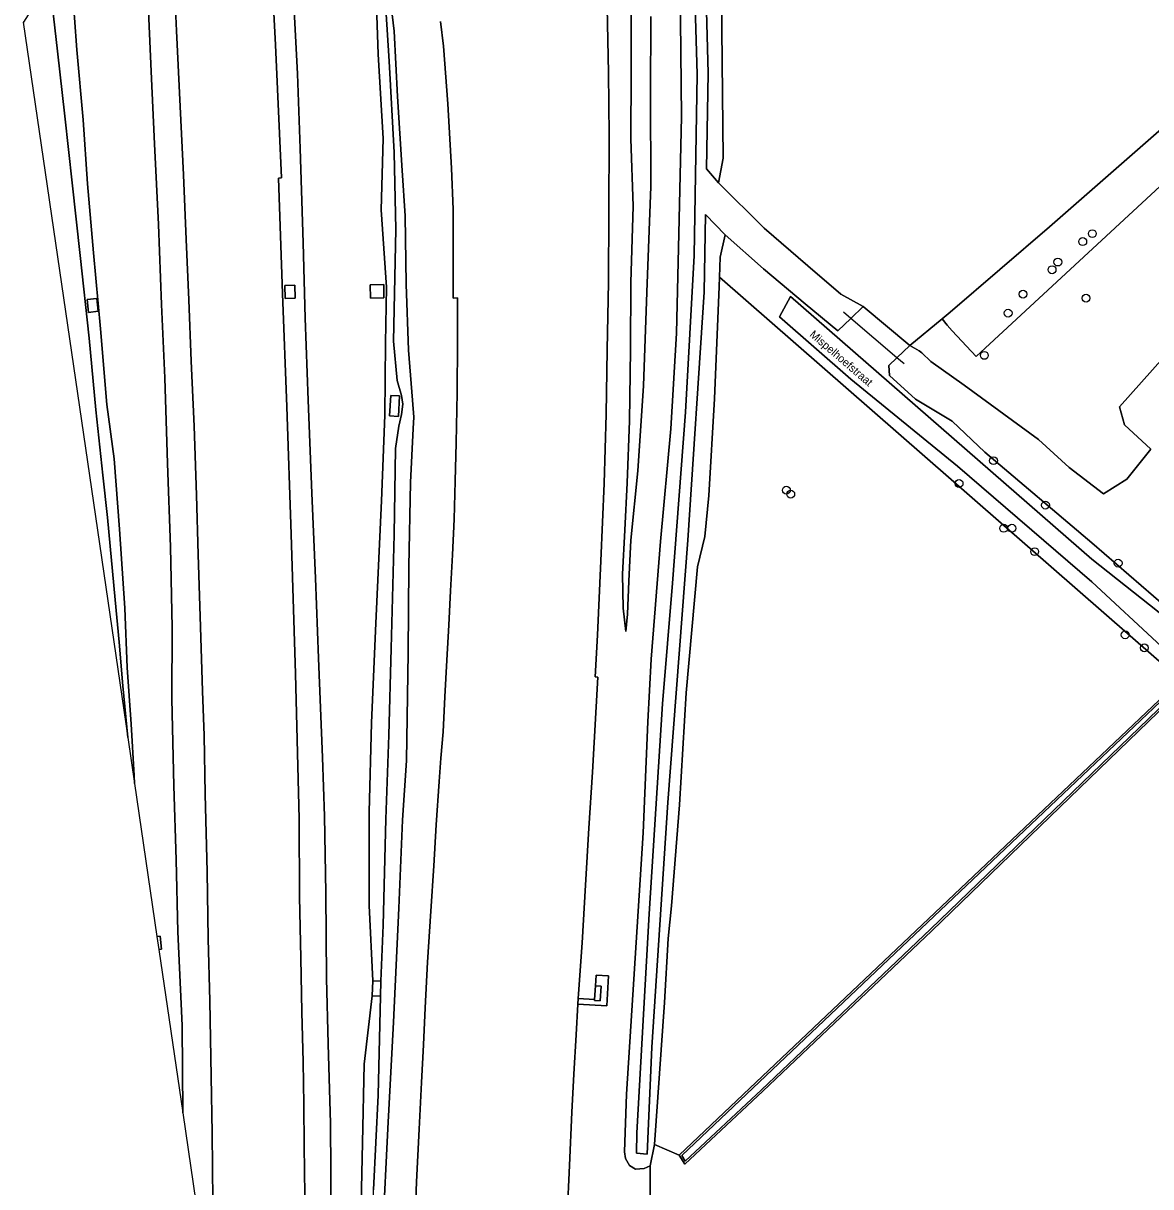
# Model space of a CAD drawing. Extents: x 156141 to 158132, y 385651 to 388333.
# Drawn here: x 156199.9 to 156340.7, y 386932.5 to 387077.9 of the extents above; entities that cross this region are included whole.
import ezdxf

# ---------------------------------------------------------------- set-up
doc = ezdxf.new("R2010")
doc.units = 0
for name, color, linetype in [('IMGEO_Berm_groen', 7, 'Continuous'), ('IMGEO_Boom', 7, 'Continuous'), ('IMGEO_Bouwland', 7, 'Continuous'), ('IMGEO_Duiker', 7, 'Continuous'), ('IMGEO_Grasland_overig', 7, 'Continuous'), ('IMGEO_Groenvoorziening', 7, 'Continuous'), ('IMGEO_Houtwal', 7, 'Continuous'), ('IMGEO_Loofbos', 7, 'Continuous'), ('IMGEO_Oever', 7, 'Continuous'), ('IMGEO_Openbare_ruimte_label', 7, 'Continuous'), ('IMGEO_Rijbaan_autosnelweg', 7, 'Continuous'), ('IMGEO_Rijbaan_lokaal_open', 7, 'Continuous'), ('IMGEO_Terreindeel_gesloten', 7, 'Continuous'), ('IMGEO_Terreindeel_open', 7, 'Continuous'), ('IMGEO_Waterloop', 7, 'Continuous')]:
    doc.layers.add(name, color=color, linetype=linetype)

msp = doc.modelspace()

# ---------------------------------------------------------------- linework, layer by layer
at = {"layer": 'IMGEO_Berm_groen'}
for points in [[(156230.11, 387099.04), (156231.36, 387075.16), (156232.14, 387058.58), (156231.74, 387058.51), (156232.25, 387044.13), (156232.79, 387029.97), (156233.33, 387014.06), (156233.86, 386996.59), (156234.31, 386978.5), (156234.39, 386968.76), (156234.53, 386961.13), (156234.68, 386954.33), (156234.83, 386948.15), (156234.92, 386942.8), (156234.97, 386937.65), (156235.04, 386931.47)], [(156223.54, 386930.73), (156223.44, 386939.22), (156223.32, 386946.32), (156223.18, 386955.74), (156222.96, 386963.51), (156222.84, 386971.85), (156222.6, 386981.59), (156222.44, 386988.92), (156222.25, 386994.44), (156222.02, 387002.46), (156221.73, 387011.49), (156221.49, 387018.92), (156221.19, 387027.55), (156220.83, 387035.68), (156220.53, 387043.33), (156220.22, 387050.85), (156219.87, 387058.94), (156219.48, 387067.48), (156219.02, 387076.94), (156218.55, 387087.03)], [(156241.87, 386920.87), (156242.26, 386938), (156242.44, 386947.86), (156243.46, 386956.36), (156243.54, 386958.27), (156243.07, 386967.68), (156243.07, 386979.31), (156243.38, 386990.48), (156243.89, 387002.95), (156244.63, 387018.21), (156245.04, 387028.93), (156245.11, 387037.93), (156245.22, 387044.91), (156244.56, 387054.56), (156244.81, 387063.48), (156244.21, 387074.03), (156243.84, 387084.86)], [(156243.84, 387084.86), (156244.21, 387074.03), (156244.81, 387063.48), (156244.56, 387054.56), (156245.22, 387044.91), (156245.11, 387037.93), (156245.04, 387028.93), (156244.63, 387018.21), (156243.89, 387002.95), (156243.38, 386990.48), (156243.07, 386979.31), (156243.07, 386967.68), (156243.54, 386958.27), (156244.55, 386958.23), (156244.82, 386965.2), (156245.14, 386978.43), (156245.51, 386988.93), (156245.81, 386999.78), (156246.19, 387014.02), (156246.37, 387024.74), (156246.8, 387027.55), (156247.13, 387029), (156247.27, 387030.28), (156247.12, 387031.38), (156246.57, 387033.25), (156246.13, 387038.15), (156246.39, 387052.12), (156246.2, 387061.74), (156245.58, 387073.13), (156244.88, 387084.28)], [(156244.88, 387084.28), (156245.58, 387073.13), (156246.2, 387061.74), (156246.39, 387052.12), (156246.13, 387038.15), (156246.57, 387033.25), (156247.12, 387031.38), (156247.27, 387030.28), (156247.13, 387029), (156246.8, 387027.55), (156246.37, 387024.74), (156246.19, 387014.02), (156245.81, 386999.78), (156245.51, 386988.93), (156245.14, 386978.43), (156244.82, 386965.2), (156244.55, 386958.23), (156244.48, 386956.32), (156244.2, 386943.98), (156243.61, 386932.16)], [(156245.34, 387084.2), (156246.21, 387076.87), (156246.63, 387068.74), (156247.18, 387059.46), (156247.56, 387053.83), (156247.69, 387045.26), (156247.98, 387037.03), (156248.48, 387030.8), (156248.66, 387028.65), (156248.58, 387027.23), (156248.22, 387020.49), (156248.04, 387010.02), (156247.94, 386999.21), (156247.74, 386985.78), (156247.23, 386978.34), (156246.79, 386967.32), (156246.13, 386953.1), (156245.41, 386939.82), (156244.78, 386927.16)], [(156244.78, 386927.16), (156245.41, 386939.82), (156246.13, 386953.1), (156246.79, 386967.32), (156247.23, 386978.34), (156247.74, 386985.78), (156247.94, 386999.21), (156248.04, 387010.02), (156248.22, 387020.49), (156248.58, 387027.23), (156248.66, 387028.65), (156248.48, 387030.8), (156247.98, 387037.03), (156247.69, 387045.26), (156247.56, 387053.83), (156247.18, 387059.46), (156246.63, 387068.74), (156246.21, 387076.87), (156245.34, 387084.2)], [(156203.13, 387083.18), (156204.13, 387074.37), (156205.05, 387066.27), (156205.96, 387057.93), (156206.98, 387048.86), (156208.1, 387038.55), (156208.94, 387029.58), (156209.8, 387021.43), (156210.39, 387016.14), (156211.32, 387005.84), (156211.83, 387000.55), (156212.31, 386995.1), (156212.93, 386988.66), (156213.77, 386982.89), (156213.7, 386983.92), (156213.33, 386990.31), (156212.83, 386997.39), (156212.55, 387004.81), (156211.9, 387014.67), (156211.22, 387023.44), (156210.3, 387030.23), (156209.51, 387039.71), (156208.64, 387049.21), (156207.9, 387057.8), (156207.35, 387065.8), (156206.54, 387074.54), (156205.96, 387082.59)], [(156205.96, 387082.59), (156206.54, 387074.54), (156207.35, 387065.8), (156207.9, 387057.8), (156208.64, 387049.21), (156209.51, 387039.71), (156210.3, 387030.23), (156211.22, 387023.44), (156211.9, 387014.67), (156212.55, 387004.81), (156212.83, 386997.39), (156213.33, 386990.31), (156213.7, 386983.92), (156213.77, 386982.89), (156216.56, 386963.8), (156216.96, 386963.84), (156217.13, 386962.19), (156216.8, 386962.16), (156219.79, 386941.75), (156219.73, 386952.67), (156219.17, 386964.39), (156218.98, 386973.36), (156218.66, 386982.61), (156218.42, 386993.46), (156218.47, 387002.34), (156218.24, 387012.48), (156217.88, 387022.86), (156217.54, 387033.57), (156217.13, 387042.74), (156216.75, 387052.73), (156216.25, 387062.81), (156215.82, 387071.83), (156215.43, 387081.34)], [(156278.19, 386927.66), (156278.18, 386935.13), (156277.42, 386934.81), (156276.36, 386934.73), (156275.59, 386935.17), (156275.11, 386936.04), (156274.96, 386936.9), (156275.23, 386944.09), (156276.56, 386965), (156277.31, 386976.73), (156277.9, 386990.61), (156278.32, 386998.43), (156279.46, 387013.13), (156280.75, 387027.19), (156281.48, 387039.14), (156281.78, 387051.59), (156282.11, 387066.19), (156281.92, 387082.37)], [(156215.43, 387081.34), (156215.82, 387071.83), (156216.25, 387062.81), (156216.75, 387052.73), (156217.13, 387042.74), (156217.54, 387033.57), (156217.88, 387022.86), (156218.24, 387012.48), (156218.47, 387002.34), (156218.42, 386993.46), (156218.66, 386982.61), (156218.98, 386973.36), (156219.17, 386964.39), (156219.73, 386952.67), (156219.79, 386941.75), (156223.72, 386914.88)], [(156238.33, 386928.47), (156238.24, 386940.43), (156237.95, 386950.4), (156237.76, 386958.53), (156237.68, 386969.24), (156237.49, 386978.82), (156237.26, 386986.15), (156236.75, 386998.56), (156236.37, 387008.55), (156235.89, 387019.17), (156235.44, 387030.78), (156235.08, 387041.03), (156234.82, 387050.44), (156234.44, 387062.24), (156234.12, 387071.54), (156233.61, 387081.07)], [(156233.61, 387081.07), (156234.12, 387071.54), (156234.44, 387062.24), (156234.82, 387050.44), (156235.08, 387041.03), (156235.44, 387030.78), (156235.89, 387019.17), (156236.37, 387008.55), (156236.75, 386998.56), (156237.26, 386986.15), (156237.49, 386978.82), (156237.68, 386969.24), (156237.76, 386958.53), (156237.95, 386950.4), (156238.24, 386940.43), (156238.33, 386928.47)], [(156272.82, 387079.84), (156272.97, 387071.68), (156273.04, 387063.84), (156273.03, 387054.28), (156272.96, 387045.54), (156272.82, 387037.08), (156272.69, 387029.06), (156272.43, 387020.37), (156272.03, 387010.73), (156271.59, 387001.44), (156271.3, 386996.21), (156271.66, 386996.19), (156270.97, 386984.3), (156270.5, 386977.34), (156270.08, 386970.19), (156269.68, 386962.99), (156269.21, 386956.64), (156269.18, 386956.04), (156271.24, 386955.91), (156271.36, 386957.61), (156271.45, 386958.95), (156272.99, 386958.89), (156272.77, 386955.12), (156269.15, 386955.32), (156268.95, 386951.52), (156268.64, 386946.58), (156268.39, 386941.84), (156268.11, 386935.2), (156267.81, 386928.96)], [(156278.28, 387078.73), (156278.24, 387068.87), (156278.26, 387057.46), (156277.78, 387044.28), (156277.35, 387032.58), (156276.64, 387021.97), (156275.78, 387013.29), (156275.52, 387008.17), (156275.36, 387004.04), (156275.13, 387001.89), (156274.8, 387004.82), (156274.72, 387009.04), (156275.02, 387014.56), (156275.32, 387020.46), (156275.61, 387028.19), (156275.72, 387037.06), (156275.78, 387045.48), (156276.04, 387055.01), (156275.78, 387063.45), (156275.8, 387071.7), (156275.81, 387080.54)], [(156248.76, 386927.56), (156248.98, 386933.14), (156249.33, 386939.71), (156249.61, 386945.56), (156249.86, 386950.24), (156250.08, 386954.87), (156250.38, 386960.57), (156250.79, 386966.94), (156251.14, 386972.63), (156251.46, 386977.76), (156251.8, 386983.17), (156252.03, 386986.06), (156252.31, 386989.35), (156252.53, 386993.75), (156252.79, 386998.32), (156253.04, 387002.68), (156253.24, 387006.98), (156253.5, 387011.47), (156253.69, 387015.94), (156253.82, 387020.67), (156253.95, 387025.47), (156254.05, 387031.69), (156254.12, 387038.04), (156254.12, 387043.59), (156253.55, 387043.52), (156253.58, 387048.5), (156253.57, 387054.59), (156253.36, 387059.76), (156252.89, 387067.8), (156252.35, 387075.03), (156252, 387078.11)]]:
    msp.add_lwpolyline(points, dxfattribs=at)
for points in [[(156232.52, 387045.12), (156233.79, 387045.16), (156233.83, 387043.52), (156232.57, 387043.49)], [(156243.21, 387045.2), (156244.89, 387045.22), (156244.91, 387043.56), (156243.24, 387043.54)], [(156209.23, 387041.89), (156208, 387041.76), (156207.83, 387043.36), (156209.05, 387043.49)], [(156245.78, 387031.39), (156246.87, 387031.32), (156246.75, 387028.76), (156245.62, 387028.84)], [(156244.48, 386956.32), (156243.46, 386956.36), (156242.44, 386947.86), (156242.26, 386938), (156241.87, 386920.87), (156241.67, 386918.94), (156241.52, 386910.28), (156241.56, 386898.49), (156241.69, 386888.21), (156241.34, 386878.23), (156241.25, 386869.17), (156241.04, 386860.9), (156241.09, 386852.14), (156241.18, 386842.52), (156241.77, 386845.93), (156241.87, 386861.43), (156242.17, 386873.83), (156242.38, 386883.71), (156242.57, 386895.07), (156242.91, 386906.95), (156243.24, 386919.54), (156243.61, 386932.16), (156244.2, 386943.98)]]:
    msp.add_lwpolyline(points, close=True, dxfattribs=at)
at = {"layer": 'IMGEO_Boom'}
for centre in [(156333.42, 387051.59), (156332.22, 387050.6), (156328.39, 387047.08), (156329.11, 387048.04), (156324.76, 387044.03), (156332.63, 387043.53), (156322.9, 387041.66), (156319.93, 387036.38), (156321.07, 387023.23), (156295.2, 387019.54), (156316.77, 387020.38), (156295.74, 387019.05), (156327.56, 387017.67), (156322.35, 387014.79), (156323.37, 387014.79), (156326.22, 387011.87), (156336.64, 387010.43), (156337.52, 387001.47), (156339.91, 386999.85)]:
    msp.add_circle(centre, 0.489, dxfattribs=at)
at = {"layer": 'IMGEO_Bouwland'}
msp.add_lwpolyline([(156267.91, 387294.21), (156273.62, 387258.67), (156274.9, 387248.17), (156277.04, 387228.59), (156278.3, 387213.58), (156280.87, 387187.34), (156283.05, 387159.61), (156284.22, 387142.35), (156285.68, 387120.79), (156286.74, 387093.34), (156287.1, 387081.16), (156287.29, 387061.02), (156286.71, 387057.93), (156292.44, 387052.28), (156297.89, 387047.57), (156302, 387044.01), (156304.8, 387042.47), (156310.61, 387037.62), (156314.65, 387040.95), (156315.67, 387041.78), (156328.06, 387052.44), (156343.41, 387065.84)], dxfattribs=at)
msp.add_lwpolyline([(156278.71, 386937.83), (156281.82, 386936.48), (156343.35, 386994.83), (156344.4, 386995.91), (156286.83, 387046.15), (156286.78, 387044.97), (156286.22, 387030.97), (156285.51, 387018.88), (156285, 387013.74), (156284.1, 387009.96), (156282.68, 386994.25), (156281.84, 386980.23), (156280.83, 386967.62), (156280.43, 386963.53), (156279.98, 386955.54)], close=True, dxfattribs=at)
at = {"layer": 'IMGEO_Duiker'}
msp.add_lwpolyline([(156309.92, 387035.31), (156309.01, 387036.09), (156303.24, 387040.99), (156302.33, 387041.77)], dxfattribs=at)
at = {"layer": 'IMGEO_Grasland_overig'}
for points in [[(156275.81, 387080.54), (156275.8, 387071.7), (156275.78, 387063.45), (156276.04, 387055.01), (156275.78, 387045.48), (156275.72, 387037.06), (156275.61, 387028.19), (156275.32, 387020.46), (156275.02, 387014.56), (156274.72, 387009.04), (156274.8, 387004.82), (156275.13, 387001.89), (156275.36, 387004.04), (156275.52, 387008.17), (156275.78, 387013.29), (156276.64, 387021.97), (156277.35, 387032.58), (156277.78, 387044.28), (156278.26, 387057.46), (156278.24, 387068.87), (156278.28, 387078.73)], [(156363.73, 387077.73), (156318.92, 387036.26), (156315.89, 387039.45), (156315.3, 387040.17), (156314.65, 387040.95), (156310.61, 387037.62), (156311.78, 387036.97), (156312.12, 387036.71)], [(156312.12, 387036.71), (156313.26, 387035.6), (156317.41, 387032.66), (156326.68, 387025.86), (156330.54, 387022.39), (156334.8, 387019.08), (156337.73, 387020.91), (156340.73, 387024.68), (156337.42, 387027.7), (156336.83, 387029.97), (156342.31, 387036.13), (156350.06, 387043.62), (156359.37, 387051.93), (156366.76, 387058.35), (156370.86, 387062.54), (156373.64, 387065.87), (156375.51, 387068.46), (156378.33, 387074.77)]]:
    msp.add_lwpolyline(points, dxfattribs=at)
at = {"layer": 'IMGEO_Groenvoorziening'}
msp.add_lwpolyline([(156342.31, 387036.13), (156336.83, 387029.97), (156337.42, 387027.7), (156340.73, 387024.68), (156337.73, 387020.91), (156334.8, 387019.08), (156330.54, 387022.39), (156326.68, 387025.86), (156317.41, 387032.66), (156313.26, 387035.6), (156312.12, 387036.71), (156311.78, 387036.97), (156310.61, 387037.62), (156309.01, 387036.09), (156307.99, 387035.11), (156308.09, 387033.85), (156311.34, 387030.92), (156315.9, 387028.17), (156320, 387024.31), (156333.35, 387012.95), (156347.22, 387000.97)], dxfattribs=at)
at = {"layer": 'IMGEO_Houtwal'}
msp.add_lwpolyline([(156314.65, 387040.95), (156315.3, 387040.17), (156315.89, 387039.45), (156318.92, 387036.26), (156363.73, 387077.73), (156366.38, 387074.9), (156406.75, 387117.43), (156403.01, 387120.86), (156400.58, 387118.69), (156387.43, 387107.44), (156382.15, 387102.12), (156374.91, 387095.52), (156354.1, 387075.81), (156343.41, 387065.84), (156328.06, 387052.44), (156315.67, 387041.78)], close=True, dxfattribs=at)
at = {"layer": 'IMGEO_Loofbos'}
for points in [[(156347.22, 387000.97), (156333.35, 387012.95), (156320, 387024.31), (156315.9, 387028.17), (156311.34, 387030.92), (156308.09, 387033.85), (156307.99, 387035.11), (156309.01, 387036.09), (156310.61, 387037.62), (156304.8, 387042.47), (156303.24, 387040.99), (156301.63, 387039.47), (156297.56, 387042.84), (156292.34, 387047.19), (156287.54, 387051.46), (156286.93, 387048.64), (156286.83, 387046.15), (156344.4, 386995.91)], [(156339.71, 386922.65), (156340.47, 386923.37), (156354.12, 386936.19), (156357.76, 386939.61), (156381.14, 386961.75), (156383.26, 386964.71), (156346.5, 386996.21), (156342.08, 387000), (156333.35, 387008.08), (156316.57, 387022.56), (156303.24, 387033.42), (156294.34, 387041.19), (156295.72, 387043.72), (156333.35, 387010.94), (156348.99, 386998.55), (156384.22, 386968.12), (156385, 386969.03), (156370.69, 386981.11), (156365.35, 386985.81)], [(156344.12, 386994.2), (156313.38, 386964.51), (156292.27, 386944.46), (156282.49, 386935.34), (156281.82, 386936.48), (156278.71, 386937.83), (156278.18, 386935.13), (156278.19, 386927.66), (156276.48, 386916.78), (156276.24, 386909.67), (156275.88, 386904.17), (156276.11, 386896.91), (156276.82, 386890.35), (156276.8, 386886.96), (156276.42, 386865.26), (156277.68, 386863.44), (156278.8, 386865.38), (156281.42, 386867.8), (156304.23, 386889.78), (156316.36, 386901.21), (156325.53, 386909.69), (156330.56, 386914.62), (156339.71, 386922.65)]]:
    msp.add_lwpolyline(points, dxfattribs=at)
at = {"layer": 'IMGEO_Oever'}
for points in [[(156269.08, 387274.43), (156272.69, 387249.63), (156275.16, 387229.01), (156278.28, 387197.8), (156281.4, 387156.9), (156284.6, 387102.69), (156285.43, 387071.64), (156285.21, 387059.68), (156286.71, 387057.93), (156287.29, 387061.02), (156287.1, 387081.16), (156286.74, 387093.34), (156285.68, 387120.79), (156284.22, 387142.35), (156283.05, 387159.61), (156280.87, 387187.34), (156278.3, 387213.58), (156277.04, 387228.59), (156274.9, 387248.17), (156273.62, 387258.67), (156267.91, 387294.21)], [(156281.92, 387082.37), (156282.11, 387066.19), (156281.78, 387051.59), (156281.48, 387039.14), (156280.75, 387027.19), (156279.46, 387013.13), (156278.32, 386998.43), (156277.9, 386990.61), (156277.31, 386976.73), (156276.56, 386965), (156275.23, 386944.09), (156274.96, 386936.9), (156275.11, 386936.04), (156275.59, 386935.17), (156276.36, 386934.73), (156277.42, 386934.81), (156278.18, 386935.13), (156278.71, 386937.83), (156279.98, 386955.54), (156280.43, 386963.53), (156280.83, 386967.62), (156281.84, 386980.23), (156282.68, 386994.25), (156284.1, 387009.96), (156285, 387013.74), (156285.51, 387018.88), (156286.22, 387030.97), (156286.78, 387044.97), (156286.83, 387046.15), (156286.93, 387048.64), (156287.54, 387051.46), (156285.11, 387053.99), (156284.93, 387044.29), (156282.88, 387013.32), (156280.37, 386980.55), (156278.4, 386949.96), (156277.79, 386936.61), (156276.46, 386936.74), (156276.52, 386939.25), (156278.04, 386966.62), (156279.72, 386992.86), (156280.95, 387007.93), (156282.6, 387029.29), (156283.67, 387048.84), (156284.03, 387071.47), (156283.62, 387085.72)], [(156379.34, 386965.6), (156366.05, 386976.84), (156346.1, 386994.5), (156345.34, 386995.13), (156344.4, 386995.91), (156343.35, 386994.83), (156281.82, 386936.48), (156282.49, 386935.34), (156292.27, 386944.46), (156313.38, 386964.51), (156344.12, 386994.2)], [(156378.6, 386964.77), (156358.18, 386982.33), (156344.45, 386994.46), (156344.02, 386994.45), (156313.21, 386964.69), (156292.1, 386944.64), (156282.54, 386935.74), (156282.14, 386936.43), (156343.52, 386994.65), (156344.42, 386995.57), (156345.18, 386994.94), (156345.94, 386994.31), (156365.89, 386976.65), (156379.18, 386965.41)]]:
    msp.add_lwpolyline(points, dxfattribs=at)
at = {"layer": 'IMGEO_Rijbaan_autosnelweg'}
for points in [[(156235.04, 386931.47), (156234.97, 386937.65), (156234.92, 386942.8), (156234.83, 386948.15), (156234.68, 386954.33), (156234.53, 386961.13), (156234.39, 386968.76), (156234.31, 386978.5), (156233.86, 386996.59), (156233.33, 387014.06), (156232.79, 387029.97), (156232.25, 387044.13), (156231.74, 387058.51), (156232.14, 387058.58), (156231.36, 387075.16), (156230.11, 387099.04)], [(156218.55, 387087.03), (156219.02, 387076.94), (156219.48, 387067.48), (156219.87, 387058.94), (156220.22, 387050.85), (156220.53, 387043.33), (156220.83, 387035.68), (156221.19, 387027.55), (156221.49, 387018.92), (156221.73, 387011.49), (156222.02, 387002.46), (156222.25, 386994.44), (156222.44, 386988.92), (156222.6, 386981.59), (156222.84, 386971.85), (156222.96, 386963.51), (156223.18, 386955.74), (156223.32, 386946.32), (156223.44, 386939.22), (156223.54, 386930.73)], [(156267.81, 386928.96), (156268.11, 386935.2), (156268.39, 386941.84), (156268.64, 386946.58), (156268.95, 386951.52), (156269.15, 386955.32), (156269.18, 386956.04), (156269.21, 386956.64), (156269.68, 386962.99), (156270.08, 386970.19), (156270.5, 386977.34), (156270.97, 386984.3), (156271.66, 386996.19), (156271.3, 386996.21), (156271.59, 387001.44), (156272.03, 387010.73), (156272.43, 387020.37), (156272.69, 387029.06), (156272.82, 387037.08), (156272.96, 387045.54), (156273.03, 387054.28), (156273.04, 387063.84), (156272.97, 387071.68), (156272.82, 387079.84)], [(156252, 387078.11), (156252.35, 387075.03), (156252.89, 387067.8), (156253.36, 387059.76), (156253.57, 387054.59), (156253.58, 387048.5), (156253.55, 387043.52), (156254.12, 387043.59), (156254.12, 387038.04), (156254.05, 387031.69), (156253.95, 387025.47), (156253.82, 387020.67), (156253.69, 387015.94), (156253.5, 387011.47), (156253.24, 387006.98), (156253.04, 387002.68), (156252.79, 386998.32), (156252.53, 386993.75), (156252.31, 386989.35), (156252.03, 386986.06), (156251.8, 386983.17), (156251.46, 386977.76), (156251.14, 386972.63), (156250.79, 386966.94), (156250.38, 386960.57), (156250.08, 386954.87), (156249.86, 386950.24), (156249.61, 386945.56), (156249.33, 386939.71), (156248.98, 386933.14), (156248.76, 386927.56)]]:
    msp.add_lwpolyline(points, dxfattribs=at)
msp.add_lwpolyline([(156212.93, 386988.66), (156212.31, 386995.1), (156211.83, 387000.55), (156211.32, 387005.84), (156210.39, 387016.14), (156209.8, 387021.43), (156208.94, 387029.58), (156208.1, 387038.55), (156206.98, 387048.86), (156205.96, 387057.93), (156205.05, 387066.27), (156204.13, 387074.37), (156203.13, 387083.18), (156199.9, 387078.01), (156199.86, 387078.01)], close=True, dxfattribs=at)
at = {"layer": 'IMGEO_Rijbaan_lokaal_open'}
msp.add_lwpolyline([(156388.39, 386964.53), (156384.22, 386968.12), (156348.99, 386998.55), (156333.35, 387010.94), (156295.72, 387043.72), (156294.34, 387041.19), (156303.24, 387033.42), (156316.57, 387022.56), (156333.35, 387008.08), (156342.08, 387000), (156346.5, 386996.21), (156383.26, 386964.71), (156389.82, 386959.09), (156415.22, 386936.95), (156419.75, 386933.01), (156421.93, 386935.45), (156418.23, 386938.75), (156407.28, 386948.21), (156401.61, 386953.1)], close=True, dxfattribs=at)
at = {"layer": 'IMGEO_Terreindeel_gesloten'}
for points in [[(156232.52, 387045.12), (156232.57, 387043.49), (156233.83, 387043.52), (156233.79, 387045.16)], [(156243.21, 387045.2), (156243.24, 387043.54), (156244.91, 387043.56), (156244.89, 387045.22)], [(156209.23, 387041.89), (156209.05, 387043.49), (156207.83, 387043.36), (156208, 387041.76)], [(156245.78, 387031.39), (156245.62, 387028.84), (156246.75, 387028.76), (156246.87, 387031.32)], [(156216.56, 386963.8), (156216.8, 386962.16), (156217.13, 386962.19), (156216.96, 386963.84)], [(156243.54, 386958.27), (156243.46, 386956.36), (156244.48, 386956.32), (156244.55, 386958.23)]]:
    msp.add_lwpolyline(points, close=True, dxfattribs=at)
at = {"layer": 'IMGEO_Terreindeel_open'}
for points in [[(156271.36, 386957.61), (156272.06, 386957.57), (156271.93, 386955.74), (156271.23, 386955.79), (156271.24, 386955.91), (156269.18, 386956.04), (156269.15, 386955.32), (156272.77, 386955.12), (156272.99, 386958.89), (156271.45, 386958.95)], [(156271.24, 386955.91), (156271.23, 386955.79), (156271.93, 386955.74), (156272.06, 386957.57), (156271.36, 386957.61)]]:
    msp.add_lwpolyline(points, close=True, dxfattribs=at)
at = {"layer": 'IMGEO_Waterloop'}
for points in [[(156283.62, 387085.72), (156284.03, 387071.47), (156283.67, 387048.84), (156282.6, 387029.29), (156280.95, 387007.93), (156279.72, 386992.86), (156278.04, 386966.62), (156276.52, 386939.25), (156276.46, 386936.74), (156277.79, 386936.61), (156278.4, 386949.96), (156280.37, 386980.55), (156282.88, 387013.32), (156284.93, 387044.29), (156285.11, 387053.99), (156287.54, 387051.46), (156292.34, 387047.19), (156297.56, 387042.84), (156301.63, 387039.47), (156303.24, 387040.99), (156304.8, 387042.47), (156302, 387044.01), (156297.89, 387047.57), (156292.44, 387052.28), (156286.71, 387057.93), (156285.21, 387059.68), (156285.43, 387071.64), (156284.6, 387102.69)], [(156379.18, 386965.41), (156365.89, 386976.65), (156345.94, 386994.31), (156345.18, 386994.94), (156344.42, 386995.57), (156343.52, 386994.65), (156282.14, 386936.43), (156282.54, 386935.74), (156292.1, 386944.64), (156313.21, 386964.69), (156344.02, 386994.45)]]:
    msp.add_lwpolyline(points, dxfattribs=at)

# ---------------------------------------------------------------- texts
at = {"layer": 'IMGEO_Openbare_ruimte_label'}
msp.add_text('Mispelhoefstraat', height=1, rotation=319.3366, dxfattribs=at).set_placement((156298.01, 387038.85))

doc.saveas('drawing.dxf')
